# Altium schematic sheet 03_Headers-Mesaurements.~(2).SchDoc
size A4; SheetNumber: 3; SheetTotal: 2
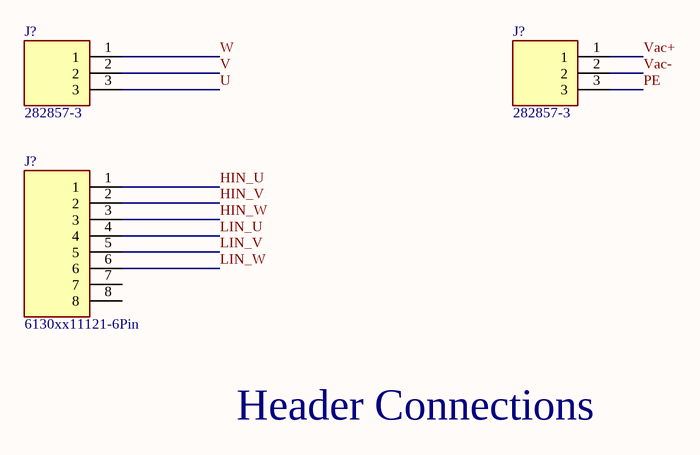
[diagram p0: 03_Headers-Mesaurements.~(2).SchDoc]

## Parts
(Parts that share a designator on the sheet are numbered #1, #2 ... from top to bottom, then left to right.)
J?#1  282857-3  [201_TE_282857-3]
J?#2  282857-3  [201_TE_282857-3]
J?#3  6130xx11121-6Pin  [200_HDRV6W64P0X254_1X6_1524X254X869P]

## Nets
HIN_U: J?#3.1
HIN_V: J?#3.2
HIN_W: J?#3.3
LIN_U: J?#3.4
LIN_V: J?#3.5
LIN_W: J?#3.6
PE: J?#2.3
U: J?#1.3
V: J?#1.2
Vac+: J?#2.1
Vac-: J?#2.2
W: J?#1.1

Not connected (* = marked no-connect by the designer): J?#3 7 8

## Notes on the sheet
- Header Connections

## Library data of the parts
J?#1 J?#2 = 282857-3: 3 Position Wire to Board Terminal Block Horizontal with Board 0.200 (5.08mm) Through Hole; MF: TE Connectivity
J?#3 = 6130xx11121-6Pin: 2.54MM PIN HEADER; Manufacturer_Name: Wurth Elektronik; Geometry.Height: 8.69mm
